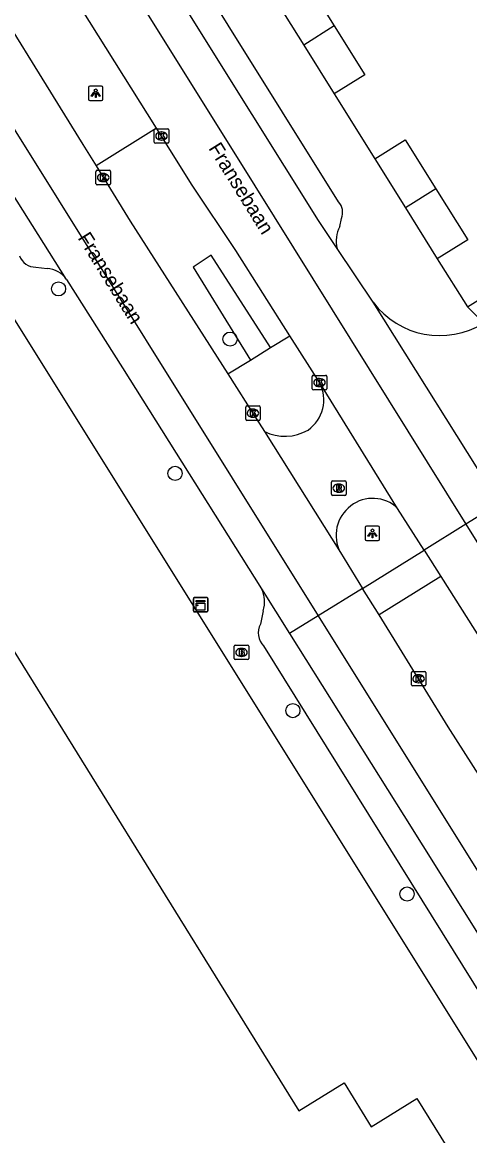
# Model space of a CAD drawing. Extents: x 158461 to 159795, y 387220 to 388672.
# Drawn here: x 158857.2 to 158888.2, y 387821.2 to 387898.2 of the extents above; entities that cross this region are included whole.
import ezdxf

# ---------------------------------------------------------------- set-up
doc = ezdxf.new("R2010")
doc.units = 0
for name, color, linetype in [('IMGEO_Berm_groen', 7, 'Continuous'), ('IMGEO_Boom', 7, 'Continuous'), ('IMGEO_Brandkraan', 7, 'Continuous'), ('IMGEO_Kast', 7, 'Continuous'), ('IMGEO_Kolk', 7, 'Continuous'), ('IMGEO_Lichtpunt', 7, 'Continuous'), ('IMGEO_Openbare_ruimte_label', 7, 'Continuous'), ('IMGEO_Pand', 7, 'Continuous'), ('IMGEO_Rijbaan_lokaal_gesloten', 7, 'Continuous'), ('IMGEO_Rijbaan_lokaal_open', 7, 'Continuous'), ('IMGEO_Rioolput', 7, 'Continuous'), ('IMGEO_Verkeerseiland_groen', 7, 'Continuous'), ('IMGEO_Voetpad_open', 7, 'Continuous')]:
    doc.layers.add(name, color=color, linetype=linetype)

msp = doc.modelspace()

# ---------------------------------------------------------------- linework, layer by layer
at = {"layer": 'IMGEO_Berm_groen'}
for points in [[(158866.508, 387890.905), (158862.321, 387888.279)], [(158874.404, 387875.711), (158870.293, 387882.102), (158869.05, 387881.273), (158873.007, 387874.851)]]:
    msp.add_lwpolyline(points, dxfattribs=at)
at = {"layer": 'IMGEO_Boom'}
for centre in [(158859.724, 387879.776), (158871.593, 387876.299), (158867.786, 387867.008), (158875.944, 387850.592), (158883.847, 387837.902)]:
    msp.add_circle(centre, 0.489, dxfattribs=at)
at = {"layer": 'IMGEO_Brandkraan'}
for p, q in [((158871.886, 387854.194), (158871.886, 387855.046)), ((158871.961, 387855.12), (158872.813, 387855.12)), ((158872.887, 387855.046), (158872.887, 387854.194)), ((158872.397, 387854.34), (158872.372, 387854.34)), ((158872.374, 387854.9), (158872.399, 387854.9)), ((158872.813, 387854.12), (158871.961, 387854.12))]:
    msp.add_line(p, q, dxfattribs=at)
for points in [[(158871.886, 387854.194), (158871.886, 387855.046)], [(158871.961, 387855.12), (158872.813, 387855.12)], [(158872.887, 387855.046), (158872.887, 387854.194)], [(158872.234, 387854.82), (158872.234, 387854.42), (158872.447, 387854.42)], [(158872.465, 387854.82), (158872.234, 387854.82)], [(158872.413, 387854.739), (158872.359, 387854.739), (158872.359, 387854.663)], [(158872.359, 387854.663), (158872.412, 387854.663)], [(158872.421, 387854.587), (158872.359, 387854.587), (158872.359, 387854.506)], [(158872.359, 387854.506), (158872.421, 387854.506)], [(158872.813, 387854.12), (158871.961, 387854.12)]]:
    msp.add_lwpolyline(points, dxfattribs=at)
for centre, radius, start, end in [((158871.963, 387855.044), 0.0765, 91.55205, 178.44795), ((158871.963, 387855.044), 0.0765, 91.55205, 178.44795), ((158872.811, 387855.044), 0.0765, 1.55205, 88.44795), ((158872.811, 387855.044), 0.0765, 1.55205, 88.44795), ((158872.414, 387854.701), 0.0379, 267.82845, 90.93552), ((158872.422, 387854.546), 0.0404, 269.87594, 90.50774), ((158872.453, 387854.671), 0.251, 268.66757, 293.53466), ((158872.469, 387854.675), 0.145, 59.4692, 91.53667), ((158872.494, 387854.722), 0.0922, 285.51372, 58.15012), ((158872.499, 387854.53), 0.105, 301.31148, 78.98903), ((158871.963, 387854.196), 0.0765, 181.55205, 268.44795), ((158871.963, 387854.196), 0.0765, 181.55205, 268.44795), ((158872.811, 387854.196), 0.0765, 271.55205, 358.44795), ((158872.811, 387854.196), 0.0765, 271.55205, 358.44795)]:
    msp.add_arc(centre, radius, start, end, dxfattribs=at)
for centre, major_axis, ratio, start_param, end_param in [((158872.373, 387854.62), (-0.387, 0.002), 0.722429, 4.712389, 7.853982), ((158872.398, 387854.62), (-0.39, 0.002), 0.717154, 1.570796, 4.712389)]:
    msp.add_ellipse(centre, major_axis=major_axis, ratio=ratio, start_param=start_param, end_param=end_param, dxfattribs=at)
at = {"layer": 'IMGEO_Kast'}
for p, q in [((158869.057, 387857.494), (158869.057, 387858.335)), ((158869.057, 387858.335), (158869.057, 387857.494)), ((158869.132, 387858.419), (158869.973, 387858.419)), ((158869.973, 387858.419), (158869.132, 387858.419)), ((158870.057, 387858.344), (158870.057, 387857.503)), ((158870.057, 387857.503), (158870.057, 387858.344)), ((158869.982, 387857.419), (158869.141, 387857.419)), ((158869.141, 387857.419), (158869.982, 387857.419))]:
    msp.add_line(p, q, dxfattribs=at)
for points in [[(158869.252, 387858.209), (158869.852, 387858.209), (158869.852, 387858.124), (158869.252, 387858.124), (158869.252, 387858.209)], [(158869.252, 387858.034), (158869.852, 387858.034), (158869.852, 387857.545), (158869.252, 387857.545), (158869.252, 387858.034)]]:
    msp.add_lwpolyline(points, dxfattribs=at)
msp.add_circle((158869.336, 387857.883), 0.0377, dxfattribs=at)
for centre, start, end in [((158869.135, 387858.341), 92.4484, 184.28452), ((158869.135, 387858.341), 92.4484, 184.28452), ((158869.979, 387858.341), 2.4484, 94.28452), ((158869.979, 387858.341), 2.4484, 94.28452), ((158869.135, 387857.497), 182.4484, 274.28452), ((158869.135, 387857.497), 182.4484, 274.28452), ((158869.979, 387857.497), 272.4484, 4.28452), ((158869.979, 387857.497), 272.4484, 4.28452)]:
    msp.add_arc(centre, 0.0779, start, end, dxfattribs=at)
at = {"layer": 'IMGEO_Kolk'}
for p, q in [((158866.351, 387889.927), (158866.351, 387890.779)), ((158866.426, 387890.853), (158867.278, 387890.853)), ((158866.839, 387890.633), (158866.864, 387890.633)), ((158867.352, 387890.779), (158867.352, 387889.927)), ((158867.278, 387889.853), (158866.426, 387889.853)), ((158866.862, 387890.073), (158866.837, 387890.073)), ((158862.316, 387887.055), (158862.316, 387887.907)), ((158862.391, 387887.981), (158863.243, 387887.981)), ((158862.804, 387887.761), (158862.829, 387887.761)), ((158863.317, 387887.907), (158863.317, 387887.055)), ((158863.243, 387886.981), (158862.391, 387886.981)), ((158862.827, 387887.201), (158862.802, 387887.201)), ((158877.287, 387872.867), (158877.287, 387873.719)), ((158877.362, 387873.793), (158878.214, 387873.793)), ((158877.775, 387873.573), (158877.8, 387873.573)), ((158878.288, 387873.719), (158878.288, 387872.867)), ((158878.214, 387872.793), (158877.362, 387872.793)), ((158877.798, 387873.013), (158877.773, 387873.013)), ((158872.679, 387870.749), (158872.679, 387871.601)), ((158872.754, 387871.675), (158873.606, 387871.675)), ((158873.167, 387871.455), (158873.192, 387871.455)), ((158873.68, 387871.601), (158873.68, 387870.749)), ((158873.606, 387870.675), (158872.754, 387870.675)), ((158873.19, 387870.895), (158873.165, 387870.895)), ((158884.147, 387852.372), (158884.147, 387853.224)), ((158884.222, 387853.298), (158885.074, 387853.298)), ((158884.635, 387853.078), (158884.66, 387853.078)), ((158885.148, 387853.224), (158885.148, 387852.372)), ((158885.074, 387852.298), (158884.222, 387852.298)), ((158884.658, 387852.518), (158884.633, 387852.518))]:
    msp.add_line(p, q, dxfattribs=at)
for points in [[(158866.351, 387889.927), (158866.351, 387890.779)], [(158866.426, 387890.853), (158867.278, 387890.853)], [(158866.672, 387890.553), (158866.795, 387890.553), (158866.795, 387890.402), (158866.925, 387890.553), (158867.089, 387890.553), (158866.943, 387890.402), (158867.096, 387890.153), (158866.944, 387890.153), (158866.859, 387890.317), (158866.795, 387890.25), (158866.795, 387890.153), (158866.672, 387890.153), (158866.672, 387890.553)], [(158867.352, 387890.779), (158867.352, 387889.927)], [(158867.278, 387889.853), (158866.426, 387889.853)], [(158862.316, 387887.055), (158862.316, 387887.907)], [(158862.391, 387887.981), (158863.243, 387887.981)], [(158862.637, 387887.681), (158862.76, 387887.681), (158862.76, 387887.53), (158862.89, 387887.681), (158863.054, 387887.681), (158862.908, 387887.53), (158863.061, 387887.281), (158862.909, 387887.281), (158862.824, 387887.445), (158862.76, 387887.378), (158862.76, 387887.281), (158862.637, 387887.281), (158862.637, 387887.681)], [(158863.317, 387887.907), (158863.317, 387887.055)], [(158863.243, 387886.981), (158862.391, 387886.981)], [(158877.287, 387872.867), (158877.287, 387873.719)], [(158877.362, 387873.793), (158878.214, 387873.793)], [(158878.288, 387873.719), (158878.288, 387872.867)], [(158878.214, 387872.793), (158877.362, 387872.793)], [(158877.608, 387873.493), (158877.731, 387873.493), (158877.731, 387873.342), (158877.861, 387873.493), (158878.025, 387873.493), (158877.879, 387873.342), (158878.032, 387873.093), (158877.88, 387873.093), (158877.795, 387873.257), (158877.731, 387873.19), (158877.731, 387873.093), (158877.608, 387873.093), (158877.608, 387873.493)], [(158872.679, 387870.749), (158872.679, 387871.601)], [(158872.754, 387871.675), (158873.606, 387871.675)], [(158873, 387871.375), (158873.123, 387871.375), (158873.123, 387871.224), (158873.253, 387871.375), (158873.417, 387871.375), (158873.271, 387871.224), (158873.424, 387870.975), (158873.272, 387870.975), (158873.187, 387871.139), (158873.123, 387871.072), (158873.123, 387870.975), (158873, 387870.975), (158873, 387871.375)], [(158873.68, 387871.601), (158873.68, 387870.749)], [(158873.606, 387870.675), (158872.754, 387870.675)], [(158884.147, 387852.372), (158884.147, 387853.224)], [(158884.222, 387853.298), (158885.074, 387853.298)], [(158884.468, 387852.998), (158884.591, 387852.998), (158884.591, 387852.847), (158884.721, 387852.998), (158884.885, 387852.998), (158884.739, 387852.847), (158884.892, 387852.598), (158884.74, 387852.598), (158884.655, 387852.762), (158884.591, 387852.695), (158884.591, 387852.598), (158884.468, 387852.598), (158884.468, 387852.998)], [(158885.148, 387853.224), (158885.148, 387852.372)], [(158885.074, 387852.298), (158884.222, 387852.298)]]:
    msp.add_lwpolyline(points, dxfattribs=at)
for centre, start, end in [((158866.428, 387890.777), 91.55205, 178.44795), ((158866.428, 387890.777), 91.55205, 178.44795), ((158867.276, 387890.777), 1.55205, 88.44795), ((158867.276, 387890.777), 1.55205, 88.44795), ((158866.428, 387889.929), 181.55205, 268.44795), ((158866.428, 387889.929), 181.55205, 268.44795), ((158867.276, 387889.929), 271.55205, 358.44795), ((158867.276, 387889.929), 271.55205, 358.44795), ((158862.393, 387887.905), 91.55205, 178.44795), ((158862.393, 387887.905), 91.55205, 178.44795), ((158863.241, 387887.905), 1.55205, 88.44795), ((158863.241, 387887.905), 1.55205, 88.44795), ((158862.393, 387887.057), 181.55205, 268.44795), ((158862.393, 387887.057), 181.55205, 268.44795), ((158863.241, 387887.057), 271.55205, 358.44795), ((158863.241, 387887.057), 271.55205, 358.44795), ((158877.364, 387873.717), 91.55205, 178.44795), ((158877.364, 387873.717), 91.55205, 178.44795), ((158878.212, 387873.717), 1.55205, 88.44795), ((158878.212, 387873.717), 1.55205, 88.44795), ((158877.364, 387872.869), 181.55205, 268.44795), ((158877.364, 387872.869), 181.55205, 268.44795), ((158878.212, 387872.869), 271.55205, 358.44795), ((158878.212, 387872.869), 271.55205, 358.44795), ((158872.756, 387871.599), 91.55205, 178.44795), ((158872.756, 387871.599), 91.55205, 178.44795), ((158873.604, 387871.599), 1.55205, 88.44795), ((158873.604, 387871.599), 1.55205, 88.44795), ((158872.756, 387870.751), 181.55205, 268.44795), ((158872.756, 387870.751), 181.55205, 268.44795), ((158873.604, 387870.751), 271.55205, 358.44795), ((158873.604, 387870.751), 271.55205, 358.44795), ((158884.224, 387853.222), 91.55205, 178.44795), ((158884.224, 387853.222), 91.55205, 178.44795), ((158885.072, 387853.222), 1.55205, 88.44795), ((158885.072, 387853.222), 1.55205, 88.44795), ((158884.224, 387852.374), 181.55205, 268.44795), ((158884.224, 387852.374), 181.55205, 268.44795), ((158885.072, 387852.374), 271.55205, 358.44795), ((158885.072, 387852.374), 271.55205, 358.44795)]:
    msp.add_arc(centre, 0.0765, start, end, dxfattribs=at)
for centre, major_axis, ratio, start_param, end_param in [((158866.838, 387890.353), (-0.387, 0.002), 0.722429, 4.712389, 7.853982), ((158866.863, 387890.353), (-0.39, 0.002), 0.717154, 1.570796, 4.712389), ((158862.803, 387887.481), (-0.387, 0.002), 0.722429, 4.712389, 7.853982), ((158862.828, 387887.481), (-0.39, 0.002), 0.717154, 1.570796, 4.712389), ((158877.774, 387873.293), (-0.387, 0.002), 0.722429, 4.712389, 7.853982), ((158877.799, 387873.293), (-0.39, 0.002), 0.717154, 1.570796, 4.712389), ((158873.166, 387871.175), (-0.387, 0.002), 0.722429, 4.712389, 7.853982), ((158873.191, 387871.175), (-0.39, 0.002), 0.717154, 1.570796, 4.712389), ((158884.634, 387852.798), (-0.387, 0.002), 0.722429, 4.712389, 7.853982), ((158884.659, 387852.798), (-0.39, 0.002), 0.717154, 1.570796, 4.712389)]:
    msp.add_ellipse(centre, major_axis=major_axis, ratio=ratio, start_param=start_param, end_param=end_param, dxfattribs=at)
at = {"layer": 'IMGEO_Lichtpunt'}
for p, q in [((158861.799, 387893.715), (158861.799, 387892.908)), ((158861.799, 387893.715), (158861.799, 387892.908)), ((158862.701, 387893.81), (158861.893, 387893.81)), ((158862.701, 387893.81), (158861.893, 387893.81)), ((158862.795, 387892.908), (158862.795, 387893.715)), ((158862.795, 387892.908), (158862.795, 387893.715)), ((158861.893, 387892.814), (158862.701, 387892.814)), ((158861.893, 387892.814), (158862.701, 387892.814)), ((158880.954, 387863.263), (158880.954, 387862.456)), ((158880.954, 387863.263), (158880.954, 387862.456)), ((158881.856, 387863.358), (158881.048, 387863.358)), ((158881.856, 387863.358), (158881.048, 387863.358)), ((158881.95, 387862.456), (158881.95, 387863.263)), ((158881.95, 387862.456), (158881.95, 387863.263)), ((158881.048, 387862.362), (158881.856, 387862.362)), ((158881.048, 387862.362), (158881.856, 387862.362))]:
    msp.add_line(p, q, dxfattribs=at)
for points in [[(158862.173, 387893.379), (158862.212, 387893.351), (158862.024, 387893.089), (158861.986, 387893.116), (158862.173, 387893.379)], [(158862.275, 387893.331), (158862.322, 387893.331), (158862.322, 387893.009), (158862.275, 387893.009), (158862.275, 387893.331)], [(158862.385, 387893.351), (158862.423, 387893.378), (158862.61, 387893.116), (158862.571, 387893.088), (158862.385, 387893.351)], [(158881.328, 387862.927), (158881.367, 387862.899), (158881.179, 387862.637), (158881.141, 387862.664), (158881.328, 387862.927)], [(158881.43, 387862.879), (158881.477, 387862.879), (158881.477, 387862.557), (158881.43, 387862.557), (158881.43, 387862.879)], [(158881.54, 387862.899), (158881.578, 387862.926), (158881.765, 387862.664), (158881.726, 387862.636), (158881.54, 387862.899)]]:
    msp.add_lwpolyline(points, dxfattribs=at)
for centre in [(158862.298, 387893.513), (158881.453, 387863.061)]:
    msp.add_circle(centre, 0.0994, dxfattribs=at)
for centre, start, end in [((158861.893, 387893.715), 90, 180), ((158861.893, 387893.715), 90, 180), ((158862.701, 387893.715), 0, 90), ((158862.701, 387893.715), 0, 90), ((158861.893, 387892.908), 180, 270), ((158861.893, 387892.908), 180, 270), ((158862.701, 387892.908), 270, 0), ((158862.701, 387892.908), 270, 360), ((158881.048, 387863.263), 90, 180), ((158881.048, 387863.263), 90, 180), ((158881.856, 387863.263), 0, 90), ((158881.856, 387863.263), 0, 90), ((158881.048, 387862.456), 180, 270), ((158881.048, 387862.456), 180, 270), ((158881.856, 387862.456), 270, 0), ((158881.856, 387862.456), 270, 360)]:
    msp.add_arc(centre, 0.0946, start, end, dxfattribs=at)
at = {"layer": 'IMGEO_Pand'}
for points in [[(158874.508, 387900.137), (158876.627, 387901.461), (158878.804, 387897.977)], [(158874.508, 387900.137), (158876.692, 387896.643)], [(158878.804, 387897.977), (158876.692, 387896.643)], [(158878.804, 387897.977), (158880.917, 387894.595), (158878.799, 387893.272)], [(158876.692, 387896.643), (158878.799, 387893.272)], [(158881.62, 387888.773), (158883.724, 387890.088), (158885.838, 387886.706)], [(158881.62, 387888.773), (158883.735, 387885.388)], [(158885.838, 387886.706), (158883.735, 387885.388)], [(158885.838, 387886.706), (158888.049, 387883.168), (158885.944, 387881.853)], [(158883.735, 387885.388), (158885.944, 387881.853)], [(158843.421, 387765.958), (158844.968, 387766.918), (158843.413, 387769.421), (158841.881, 387768.47), (158822.272, 387800.049), (158819.635, 387804.296), (158853.129, 387825.094), (158836.694, 387851.56), (158837.362, 387851.975), (158838.447, 387850.227), (158852.702, 387859.079), (158851.58, 387860.885), (158852.446, 387861.423), (158876.367, 387822.901), (158879.485, 387824.836), (158881.375, 387821.792), (158884.521, 387823.745), (158904.752, 387791.165), (158903.336, 387790.286), (158904.922, 387787.732), (158906.392, 387788.644), (158919.073, 387768.222), (158912.998, 387764.449), (158909.819, 387762.475)]]:
    msp.add_lwpolyline(points, dxfattribs=at)
at = {"layer": 'IMGEO_Rijbaan_lokaal_gesloten'}
for points in [[(158777.679, 388039.896), (158792.31, 388017.418), (158834.227, 387949.391), (158871.964, 387889.05), (158887.922, 387863.502)], [(158774.869, 388017.05), (158778.332, 388014.385), (158779.563, 388013.342), (158780.694, 388012.384), (158785.095, 388005.301), (158793.995, 387991.082), (158802.455, 387977.515), (158810.737, 387964.275), (158822.801, 387944.946), (158836.678, 387922.775), (158853.754, 387895.444), (158877.701, 387857.148)], [(158860.281, 387880.424), (158855.269, 387888.326), (158848.058, 387899.934), (158837.312, 387917.021), (158827.094, 387933.478), (158816.677, 387949.935), (158806.829, 387965.972), (158797.5, 387980.78), (158793.285, 387987.639), (158789.331, 387993.838), (158785.494, 388000), (158780.215, 388008.468)], [(158879.01, 387882.568), (158877.715, 387884.504), (158870.764, 387895.592), (158857.71, 387916.557), (158844.256, 387938.083), (158828.405, 387963.308), (158826.242, 387967.003)], [(158866.508, 387890.905), (158858.993, 387902.895), (158857.412, 387905.443)], [(158853.284, 387902.882), (158861.396, 387889.771), (158862.321, 387888.279)], [(158875.735, 387876.531), (158871.986, 387882.438), (158868.981, 387886.958), (158866.508, 387890.905)], [(158862.321, 387888.279), (158864.683, 387884.472), (158871.444, 387873.889)], [(158881.497, 387878.849), (158879.01, 387882.568)], [(158860.281, 387880.424), (158864.153, 387874.318), (158873.777, 387859.01)], [(158890.244, 387864.932), (158881.497, 387878.849)], [(158877.803, 387873.273), (158875.735, 387876.531)], [(158871.444, 387873.889), (158873.407, 387870.816), (158873.975, 387869.911)], [(158883.193, 387864.581), (158877.803, 387873.273)], [(158873.975, 387869.911), (158879.233, 387861.53)], [(158885.025, 387861.694), (158883.193, 387864.581)], [(158890.244, 387864.932), (158887.922, 387863.502)], [(158887.922, 387863.502), (158885.025, 387861.694)], [(158887.922, 387863.502), (158910.852, 387826.792), (158942.469, 387776.24), (158958.617, 387750.353), (158960.418, 387747.762), (158961.612, 387746.321), (158963.393, 387744.535), (158965.421, 387742.895), (158967.458, 387741.572), (158969.689, 387740.407), (158971.94, 387739.465), (158974.416, 387738.664), (158976.417, 387738.226), (158979.369, 387737.931), (158981.889, 387737.858), (159007.45, 387739.32), (159019.867, 387740.171), (159032.856, 387742.163)], [(158879.233, 387861.53), (158880.768, 387859.054)], [(158885.025, 387861.694), (158886.183, 387859.869)], [(158886.183, 387859.869), (158892.214, 387850.364), (158894.338, 387846.957)], [(158873.777, 387859.01), (158875.717, 387855.924)], [(158880.768, 387859.054), (158877.701, 387857.148)], [(158881.907, 387857.218), (158880.768, 387859.054)], [(158877.701, 387857.148), (158875.717, 387855.924)], [(158877.701, 387857.148), (158898.064, 387824.564), (158950.111, 387741.221), (158948.001, 387740.023)], [(158890.044, 387844.243), (158886.705, 387849.479), (158881.907, 387857.218)], [(158875.717, 387855.924), (158883.633, 387843.333), (158898.324, 387819.878), (158900.577, 387816.28), (158919.568, 387785.998), (158934.623, 387761.938), (158942.187, 387750), (158945.11, 387745.294), (158947.991, 387740.043)]]:
    msp.add_lwpolyline(points, dxfattribs=at)
at = {"layer": 'IMGEO_Rijbaan_lokaal_open'}
for centre, radius, start, end in [((158886.119, 387882.323), 5.781, 216.9301, 301.64717), ((158875.525, 387872.104), 2.561, 305.11972, 27.17155), ((158875.397, 387872.722), 3.15, 243.16457, 300.54897), ((158881.472, 387862.819), 2.463, 45.68552, 128.05867), ((158881.466, 387862.726), 2.533, 126.65414, 208.16423)]:
    msp.add_arc(centre, radius, start, end, dxfattribs=at)
at = {"layer": 'IMGEO_Rioolput'}
for p, q in [((158878.622, 387865.56), (158878.622, 387866.412)), ((158878.697, 387866.486), (158879.549, 387866.486)), ((158879.11, 387866.266), (158879.135, 387866.266)), ((158879.623, 387866.412), (158879.623, 387865.56)), ((158879.549, 387865.486), (158878.697, 387865.486)), ((158879.133, 387865.706), (158879.108, 387865.706))]:
    msp.add_line(p, q, dxfattribs=at)
for points in [[(158878.622, 387865.56), (158878.622, 387866.412)], [(158878.697, 387866.486), (158879.549, 387866.486)], [(158879.211, 387866.184), (158878.959, 387866.186), (158878.959, 387865.786)], [(158878.959, 387865.786), (158879.083, 387865.786), (158879.083, 387865.948), (158879.094, 387865.948)], [(158879.137, 387866.105), (158879.083, 387866.105), (158879.083, 387866.024)], [(158879.083, 387866.024), (158879.135, 387866.024)], [(158879.141, 387865.919), (158879.212, 387865.786), (158879.352, 387865.786), (158879.287, 387865.912)], [(158879.623, 387866.412), (158879.623, 387865.56)], [(158879.549, 387865.486), (158878.697, 387865.486)]]:
    msp.add_lwpolyline(points, dxfattribs=at)
for centre, radius, start, end in [((158878.699, 387866.41), 0.0765, 91.55205, 178.44795), ((158878.699, 387866.41), 0.0765, 91.55205, 178.44795), ((158879.093, 387865.895), 0.0533, 26.02933, 88.69889), ((158879.119, 387866.213), 0.19, 274.7715, 282.96867), ((158879.143, 387866.009), 0.0964, 77.00612, 93.18647), ((158879.157, 387866.066), 0.0378, 276.66336, 79.67722), ((158879.21, 387866.074), 0.109, 350.36119, 89.41601), ((158879.208, 387866.074), 0.112, 277.58423, 350.98172), ((158879.192, 387865.859), 0.108, 29.51342, 73.79051), ((158879.547, 387866.41), 0.0765, 1.55205, 88.44795), ((158879.547, 387866.41), 0.0765, 1.55205, 88.44795), ((158878.699, 387865.562), 0.0765, 181.55205, 268.44795), ((158878.699, 387865.562), 0.0765, 181.55205, 268.44795), ((158879.547, 387865.562), 0.0765, 271.55205, 358.44795), ((158879.547, 387865.562), 0.0765, 271.55205, 358.44795)]:
    msp.add_arc(centre, radius, start, end, dxfattribs=at)
for centre, major_axis, ratio, start_param, end_param in [((158879.109, 387865.986), (-0.387, 0.002), 0.722429, 4.712389, 7.853982), ((158879.134, 387865.986), (-0.39, 0.002), 0.717154, 1.570796, 4.712389)]:
    msp.add_ellipse(centre, major_axis=major_axis, ratio=ratio, start_param=start_param, end_param=end_param, dxfattribs=at)
at = {"layer": 'IMGEO_Verkeerseiland_groen'}
for points in [[(158874.404, 387875.711), (158875.735, 387876.531)], [(158873.007, 387874.851), (158874.404, 387875.711)], [(158871.444, 387873.889), (158873.007, 387874.851)]]:
    msp.add_lwpolyline(points, dxfattribs=at)
at = {"layer": 'IMGEO_Voetpad_open'}
for points in [[(158879.11, 387885.808), (158829.151, 387965.739)], [(158878.799, 387893.272), (158881.62, 387888.773)], [(158888.037, 387878.531), (158905.701, 387889.612), (158905.813, 387889.502)], [(158879.185, 387884.094), (158879.312, 387884.652)], [(158858.154, 387881.281), (158858.928, 387881.191)], [(158885.944, 387881.853), (158888.037, 387878.531)], [(158946.265, 387734.359), (158945.05, 387736.345), (158936.552, 387750), (158894.251, 387817.603), (158856.23, 387878.364)], [(158888.037, 387878.531), (158889.152, 387877.401)], [(158880.768, 387859.054), (158885.025, 387861.694)], [(158886.183, 387859.869), (158881.907, 387857.218)], [(158873.883, 387857.503), (158873.705, 387856.576)], [(158873.919, 387855.065), (158896.474, 387818.845), (158939.346, 387750), (158944.861, 387741.144)]]:
    msp.add_lwpolyline(points, dxfattribs=at)
for centre, radius, start, end in [((158878.261, 387885.064), 1.129, 338.6075, 41.21613), ((158881.161, 387883.094), 2.215, 153.16653, 193.7494), ((158858.144, 387882.488), 1.207, 200.37615, 270.47914), ((158858.837, 387879.453), 1.74, 33.91304, 86.99016), ((158872.025, 387858.13), 1.96, 341.36098, 26.68596), ((158874.849, 387855.967), 1.296, 151.99579, 224.12636)]:
    msp.add_arc(centre, radius, start, end, dxfattribs=at)

# ---------------------------------------------------------------- texts
at = {"layer": 'IMGEO_Openbare_ruimte_label'}
for p in [(158870.071, 387889.509), (158861.019, 387883.303)]:
    msp.add_text('Fransebaan', height=1, rotation=301.87782, dxfattribs=at).set_placement(p)

doc.saveas('drawing.dxf')
